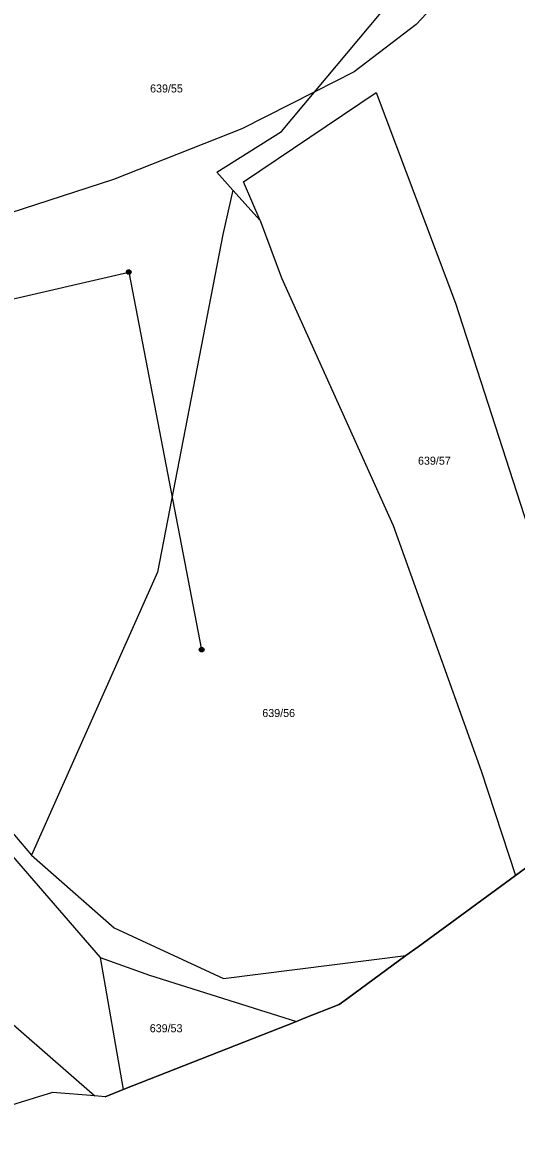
# Model space of a CAD drawing. Extents: x -759699 to -757730, y -1172308 to -1170857.
# Drawn here: x -758654.9 to -758550, y -1171635.6 to -1171396.5 of the extents above; entities that cross this region are included whole.
import ezdxf

# ---------------------------------------------------------------- set-up
doc = ezdxf.new("R2010")
doc.units = 0
for name, color, linetype in [('Vrstva 1', 7, 'Continuous'), ('Vrstva 11', 7, 'Continuous'), ('Vrstva 2', 7, 'Continuous'), ('Vrstva 6', 7, 'Continuous')]:
    doc.layers.add(name, color=color, linetype=linetype)

msp = doc.modelspace()

# ---------------------------------------------------------------- linework, layer by layer
at = {"layer": 'Vrstva 1'}
for p, q in [((-758599.91, -1171419.66), (-758576.55, -1171391.75)), ((-758607.95, -1171430.3), (-758579.79, -1171411.37)), ((-758579.79, -1171411.37), (-758562.96, -1171456.1)), ((-758613.6, -1171428.27), (-758599.91, -1171419.66)), ((-758613.6, -1171428.27), (-758610.2, -1171432.12)), ((-758610.2, -1171432.12), (-758612.34, -1171441.49)), ((-758610.2, -1171432.12), (-758604.42, -1171438.53)), ((-758604.42, -1171438.53), (-758607.95, -1171430.3)), ((-758604.42, -1171438.53), (-758599.88, -1171450.69)), ((-758612.34, -1171441.49), (-758626.22, -1171513.23)), ((-758599.88, -1171450.69), (-758576.2, -1171503.33)), ((-758562.96, -1171456.1), (-758543.32, -1171516.87)), ((-758576.2, -1171503.33), (-758557.49, -1171555.42)), ((-758626.22, -1171513.23), (-758653, -1171573.28)), ((-758696.58, -1171522.37), (-758653, -1171573.28)), ((-758557.49, -1171555.42), (-758550.16, -1171577.59)), ((-758665.47, -1171563.8), (-758638.43, -1171595.06)), ((-758550.16, -1171577.59), (-758534.83, -1171566.37)), ((-758653, -1171573.28), (-758635.41, -1171588.72)), ((-758570.86, -1171592.74), (-758550.16, -1171577.59)), ((-758635.41, -1171588.72), (-758612.21, -1171599.5)), ((-758612.21, -1171599.5), (-758573.45, -1171594.63)), ((-758585.85, -1171603.71), (-758573.45, -1171594.63)), ((-758573.45, -1171594.63), (-758570.86, -1171592.74)), ((-758671.94, -1171596.19), (-758639.52, -1171624.42)), ((-758638.43, -1171595.06), (-758633.51, -1171623.08)), ((-758638.43, -1171595.06), (-758627.95, -1171598.76)), ((-758627.95, -1171598.76), (-758596.72, -1171608.6)), ((-758587.67, -1171605.04), (-758585.85, -1171603.71)), ((-758595.2, -1171608), (-758587.67, -1171605.04)), ((-758633.51, -1171623.08), (-758596.72, -1171608.6)), ((-758596.72, -1171608.6), (-758595.2, -1171608)), ((-758637.34, -1171624.59), (-758633.51, -1171623.08)), ((-758648.55, -1171623.71), (-758686.97, -1171635.59)), ((-758639.52, -1171624.42), (-758648.55, -1171623.71)), ((-758637.34, -1171624.59), (-758639.52, -1171624.42))]:
    msp.add_line(p, q, dxfattribs=at)
at = {"layer": 'Vrstva 11'}
for p, q in [((-758553.56, -1171377.79), (-758571.28, -1171396.93)), ((-758571.28, -1171396.93), (-758584.49, -1171406.98)), ((-758584.49, -1171406.98), (-758592.84, -1171411.21)), ((-758592.84, -1171411.21), (-758608.33, -1171419.07)), ((-758608.33, -1171419.07), (-758635.54, -1171429.85)), ((-758635.54, -1171429.85), (-758673.8, -1171442.25)), ((-758534.83, -1171566.37), (-758550.16, -1171577.59)), ((-758550.16, -1171577.59), (-758570.86, -1171592.74)), ((-758573.45, -1171594.63), (-758585.85, -1171603.71)), ((-758570.86, -1171592.74), (-758573.45, -1171594.63)), ((-758585.85, -1171603.71), (-758587.67, -1171605.04)), ((-758587.67, -1171605.04), (-758595.2, -1171608)), ((-758596.72, -1171608.6), (-758633.51, -1171623.08)), ((-758595.2, -1171608), (-758596.72, -1171608.6)), ((-758633.51, -1171623.08), (-758637.34, -1171624.59)), ((-758648.55, -1171623.71), (-758686.97, -1171635.59)), ((-758639.52, -1171624.42), (-758648.55, -1171623.71)), ((-758637.34, -1171624.59), (-758639.52, -1171624.42))]:
    msp.add_line(p, q, dxfattribs=at)
at = {"layer": 'Vrstva 6'}
for p, q in [((-758692.22, -1171463.37), (-758632.34, -1171449.48)), ((-758632.34, -1171449.48), (-758632.34, -1171449.48)), ((-758632.34, -1171449.48), (-758616.86, -1171529.68))]:
    msp.add_line(p, q, dxfattribs=at)
for points in [[(-758632.49, -1171449), (-758632.18, -1171449), (-758631.93, -1171449.18), (-758631.83, -1171449.47), (-758631.93, -1171449.76), (-758632.18, -1171449.94), (-758632.49, -1171449.94), (-758632.74, -1171449.76), (-758632.84, -1171449.47), (-758632.74, -1171449.18), (-758632.49, -1171449), (-758632.46, -1171449.04), (-758632.22, -1171449.04), (-758632.06, -1171449.12), (-758632.62, -1171449.12), (-758632.7, -1171449.2), (-758631.98, -1171449.2), (-758631.98, -1171449.28), (-758632.7, -1171449.28), (-758632.74, -1171449.36), (-758631.94, -1171449.36), (-758631.9, -1171449.44), (-758632.78, -1171449.44), (-758632.78, -1171449.52), (-758631.9, -1171449.52), (-758631.93, -1171449.6), (-758632.74, -1171449.6), (-758632.73, -1171449.68), (-758631.92, -1171449.68), (-758631.97, -1171449.76), (-758632.69, -1171449.76), (-758632.61, -1171449.84), (-758632.05, -1171449.84), (-758632.16, -1171449.92), (-758632.5, -1171449.92)], [(-758617.01, -1171529.2), (-758616.7, -1171529.2), (-758616.45, -1171529.38), (-758616.35, -1171529.67), (-758616.45, -1171529.96), (-758616.7, -1171530.14), (-758617.01, -1171530.14), (-758617.26, -1171529.96), (-758617.36, -1171529.67), (-758617.26, -1171529.38), (-758617.01, -1171529.2), (-758616.98, -1171529.24), (-758616.74, -1171529.24), (-758616.58, -1171529.32), (-758617.14, -1171529.32), (-758617.22, -1171529.4), (-758616.5, -1171529.4), (-758616.5, -1171529.48), (-758617.22, -1171529.48), (-758617.26, -1171529.56), (-758616.46, -1171529.56), (-758616.42, -1171529.64), (-758617.3, -1171529.64), (-758617.3, -1171529.72), (-758616.42, -1171529.72), (-758616.45, -1171529.8), (-758617.26, -1171529.8), (-758617.25, -1171529.88), (-758616.44, -1171529.88), (-758616.49, -1171529.96), (-758617.21, -1171529.96), (-758617.13, -1171530.04), (-758616.57, -1171530.04), (-758616.68, -1171530.12), (-758617.02, -1171530.12)]]:
    msp.add_lwpolyline(points, dxfattribs=at)

# ---------------------------------------------------------------- texts
at = {"layer": 'Vrstva 2'}
for s, p in [('639/55', (-758627.803, -1171411.34)), ('639/57', (-758570.896, -1171490.39)), ('639/56', (-758603.966, -1171543.97)), ('639/53', (-758627.873, -1171610.91))]:
    msp.add_text(s, height=1.7, dxfattribs=at).set_placement(p)

doc.saveas('drawing.dxf')
